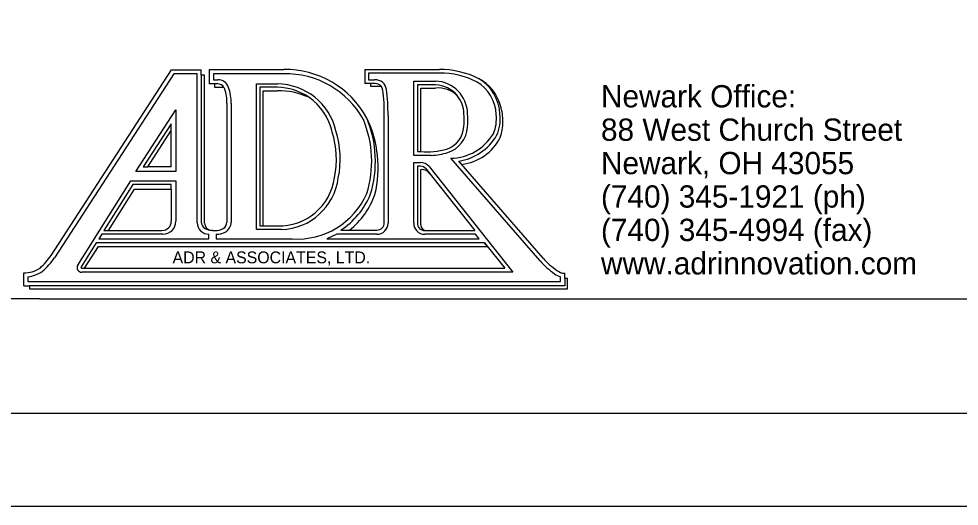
# Model space of a CAD drawing. Extents: x 0 to 2329303, y 0 to 694397.
# Drawn here: x 2.57 to 7.64, y 0 to 2.63 of the extents above; entities that cross this region are included whole.
import ezdxf

# ---------------------------------------------------------------- set-up
doc = ezdxf.new("R2010")
doc.units = 0
for name, color, linetype in [('SH_Border', 7, 'Continuous'), ('SH_Cut_Line', 7, 'Continuous'), ('SH_Data', 7, 'Continuous')]:
    doc.layers.add(name, color=color, linetype=linetype)

msp = doc.modelspace()

# ---------------------------------------------------------------- linework, layer by layer
at = {"layer": 'SH_Border'}
msp.add_lwpolyline([(1.5, 21.5), (33.5, 21.5), (33.5, 0.5), (1.5, 0.5)], close=True, dxfattribs=at)
at = {"layer": 'SH_Cut_Line'}
msp.add_lwpolyline([(0, 0), (34, 0), (34, 22), (0, 22)], close=True, dxfattribs=at)
at = {"layer": 'SH_Data'}
for p, q in [((2.7482, 1.3509), (3.3982, 2.3517)), ((3.3982, 2.3517), (3.5581, 2.3517)), ((3.5581, 2.3218), (3.5581, 2.3517)), ((3.6, 2.3529), (3.6, 2.2749)), ((3.6, 2.3529), (4.0021, 2.3529)), ((4.44, 2.3529), (4.44, 2.2778)), ((4.44, 2.3529), (4.8421, 2.3529)), ((3.63, 2.2749), (3.6, 2.2749)), ((4.47, 2.2778), (4.44, 2.2778)), ((3.6962, 2.1694), (3.6962, 1.5311)), ((4.5443, 1.5273), (4.5443, 2.1043)), ((3.3962, 1.828), (3.3962, 2.0237)), ((3.3962, 1.828), (3.2691, 1.828)), ((5.3998, 1.336), (4.9458, 1.8587)), ((4.7723, 1.814), (5.0329, 1.4852)), ((3.3962, 1.708), (3.3962, 1.5353)), ((3.0573, 1.4853), (3.3462, 1.4853)), ((3.6177, 1.4852), (3.6118, 1.4857)), ((3.6177, 1.4852), (3.6324, 1.4852)), ((3.8913, 1.5107), (3.9682, 1.5107)), ((4.3102, 1.4873), (4.5043, 1.4873)), ((4.7627, 1.4852), (5.0329, 1.4852)), ((5.0844, 1.4193), (5.1932, 1.2816)), ((2.9289, 1.2816), (5.1932, 1.2816)), ((2.6013, 1.1881), (2.6013, 1.2567)), ((5.5167, 1.2268), (5.5167, 1.2553)), ((2.6013, 1.1881), (2.6318, 1.1881)), ((2.6879, 1.1163), (2.2843, 1.1163)), ((2.6879, 1.1163), (7.8956, 1.1163))]:
    msp.add_line(p, q, dxfattribs=at)
for points in [[(4.8421, 2.3329), (4.46, 2.3329), (4.46, 2.2978), (4.4918, 2.2978)], [(3.5361, 1.5275), (3.5361, 2.3297), (3.4101, 2.3297), (2.7667, 1.3389)], [(3.5761, 1.5255), (3.5761, 2.3218), (3.5581, 2.3218), (3.5581, 1.5311)], [(4.0021, 2.3297), (3.6232, 2.3297), (3.6232, 2.2975), (3.6464, 2.2975)], [(4.7027, 2.2904), (4.8216, 2.2904)], [(4.7974, 1.8901), (4.7027, 1.8901), (4.7027, 2.2904)], [(3.6464, 2.2749), (3.63, 2.2749), (3.63, 2.2569), (3.6798, 2.2569)], [(3.8556, 1.49), (3.8556, 2.2749), (3.9682, 2.2749)], [(3.9682, 2.2569), (3.8733, 2.2569), (3.8733, 1.5107), (3.8913, 1.5107), (3.8913, 2.2386), (3.9682, 2.2386)], [(4.4864, 2.2778), (4.47, 2.2778), (4.47, 2.2623), (4.5279, 2.2623)], [(4.8212, 2.2704), (4.7227, 2.2704), (4.7227, 1.9117)], [(4.7407, 1.9101), (4.7407, 2.2524), (4.8212, 2.2524)], [(3.4212, 1.803), (3.2052, 1.803), (3.4212, 2.1356), (3.4212, 1.803)], [(3.7188, 2.1694), (3.7188, 2.1685), (3.7188, 1.5311)], [(4.5643, 2.1041), (4.5643, 1.5252)], [(3.3962, 2.0237), (3.3962, 2.0604), (3.2453, 1.828), (3.2691, 1.828), (3.3962, 2.0237)], [(4.7857, 1.8293), (5.2369, 1.2601), (2.9134, 1.2601)], [(4.7027, 1.5252), (4.7027, 1.852), (4.7387, 1.852)], [(4.7387, 1.832), (4.7227, 1.832), (4.7227, 1.5252)], [(5.3836, 1.3211), (4.9027, 1.8749)], [(4.9458, 1.8587), (4.9608, 1.8414)], [(4.7407, 1.5152), (4.7407, 1.814), (4.7433, 1.814)], [(4.7903, 1.7913), (4.7701, 1.8168)], [(2.8922, 1.2985), (3.1787, 1.753), (3.4212, 1.753), (3.4212, 1.5353)], [(3.3962, 1.708), (3.3962, 1.733), (3.1897, 1.733), (3.0336, 1.4853), (3.0573, 1.4853), (3.1976, 1.708), (3.3962, 1.708)], [(3.9896, 1.49), (3.8556, 1.49)], [(4.3102, 1.4873), (4.3567, 1.4873)], [(4.7627, 1.4852), (4.7707, 1.4852)], [(5.1002, 1.3993), (5.0844, 1.4193), (2.992, 1.4193), (2.9101, 1.2892)], [(3.3512, 1.4653), (3.0213, 1.4653), (3.0056, 1.4403), (3.5984, 1.4403), (3.5984, 1.4653)], [(3.6387, 1.4653), (3.6387, 1.4403), (4.0488, 1.4403)], [(4.5043, 1.4652), (4.2885, 1.4652), (4.2339, 1.4403), (5.0563, 1.4403), (5.0366, 1.4652), (4.7627, 1.4652)], [(2.9143, 1.2816), (2.9289, 1.2816), (3.0031, 1.3993), (5.1002, 1.3993)], [(2.6233, 1.236), (2.6233, 1.2101), (5.4947, 1.2101), (5.4947, 1.2361)], [(5.5167, 1.2268), (5.5167, 1.1881), (2.6318, 1.1881), (2.6318, 1.1717), (5.5315, 1.1717), (5.5315, 1.2268), (5.5167, 1.2268)]]:
    msp.add_lwpolyline(points, dxfattribs=at)
for centre, radius, start, end in [((4.0092, 1.8512), 0.5017, 28.5037, 90.8094), ((4.847, 1.9007), 0.4522, 62.8944, 90.6455), ((4.8473, 1.9019), 0.431, 63.1652, 90.6924), ((3.6464, 2.2349), 0.0626, 19.9599, 90), ((4.0128, 1.8511), 0.4787, 28.9697, 91.2754), ((4.4889, 2.2142), 0.0836, 56.3608, 88.0126), ((4.495, 2.2381), 0.0608, 6.9031, 48.6696), ((4.8134, 2.1105), 0.1801, 1.5931, 87.3658), ((4.9344, 2.1021), 0.2134, 2.1717, 59.7559), ((4.946, 2.0969), 0.2324, 14.8093, 62.8819), ((4.9344, 2.1021), 0.2334, 2.3391, 59.7559), ((4.946, 2.0969), 0.2324, 14.8093, 62.8819), ((4.9344, 2.1021), 0.2334, 2.3391, 59.7559), ((3.6464, 2.2349), 0.04, 33.367, 90), ((3.6464, 2.2349), 0.04, 19.9599, 33.367), ((3.4897, 2.178), 0.2067, 357.6357, 19.9599), ((3.4897, 2.178), 0.2293, 357.8689, 19.9599), ((3.9661, 1.9493), 0.3256, 12.9457, 89.6392), ((3.9638, 1.9496), 0.3073, 55.708, 89.1774), ((3.9693, 1.8209), 0.4177, 66.3384, 90.1529), ((4.4889, 2.2142), 0.0636, 57.6105, 92.2784), ((4.495, 2.2381), 0.0408, 36.3055, 46.8401), ((4.495, 2.2381), 0.0408, 6.5993, 36.3055), ((3.6945, 2.1203), 0.85, 358.9246, 8.2892), ((3.6945, 2.1203), 0.87, 358.937, 8.2716), ((4.8134, 2.1105), 0.1601, 39.5541, 87.2061), ((4.8356, 2.1069), 0.1462, 46.2019, 95.6746), ((3.9638, 1.9496), 0.3073, 12.4839, 55.708), ((4.8134, 2.1105), 0.1601, 1.5931, 39.5541), ((4.9219, 2.0761), 0.2614, 358.8465, 17.8591), ((3.8896, 1.8582), 0.5868, 342.7269, 22.5268), ((3.9047, 1.8246), 0.6068, 346.2054, 26.0053), ((3.8896, 1.8582), 0.6068, 342.7269, 22.5268), ((3.8896, 1.8582), 0.6068, 342.7269, 22.5268), ((3.9047, 1.8246), 0.6068, 346.2054, 26.0053), ((4.5969, 2.0827), 0.3779, 354.0254, 4.8885), ((4.6077, 2.0826), 0.3871, 354.0167, 4.8798), ((4.9391, 2.088), 0.2098, 336.9308, 6.0804), ((4.9391, 2.088), 0.2298, 336.5619, 5.9102), ((4.9391, 2.088), 0.2298, 336.5619, 5.9102), ((4.8385, 2.0514), 0.1345, 288.9475, 356.593), ((4.8375, 2.0522), 0.1555, 288.6824, 356.328), ((4.9411, 2.0671), 0.2422, 340.715, 0.8874), ((4.9411, 2.0671), 0.2422, 340.715, 0.8874), ((3.7992, 1.8701), 0.487, 348.269, 17.4361), ((3.8022, 1.8702), 0.5047, 348.3549, 17.522), ((4.8983, 2.1489), 0.2741, 270.9085, 328.5097), ((4.8983, 2.1489), 0.2941, 279.2997, 328.7949), ((4.8983, 2.1489), 0.2941, 279.2997, 328.7949), ((4.9306, 2.1074), 0.2677, 276.4841, 333.2931), ((4.9306, 2.1074), 0.2677, 276.4841, 333.2931), ((4.7687, 2.3469), 0.4377, 263.9631, 266.3281), ((4.7687, 2.3469), 0.4377, 266.3281, 285.024), ((4.7687, 2.3469), 0.4577, 273.5907, 285.024), ((4.7387, 1.792), 0.06, 38.4038, 90), ((4.7387, 1.792), 0.04, 38.4038, 90), ((4.7433, 1.754), 0.06, 38.4038, 90), ((3.9789, 1.8102), 0.2997, 267.9548, 352.4953), ((3.9789, 1.8102), 0.3204, 271.9132, 352.4953), ((4.0753, 1.8488), 0.4093, 266.2973, 336.2434), ((4.075, 1.8445), 0.4277, 303.356, 337.0819), ((4.0907, 1.8222), 0.4277, 308.4519, 340.5604), ((3.3462, 1.5353), 0.05, 270, 0), ((3.3512, 1.5353), 0.07, 270, 0), ((3.5983, 1.5275), 0.0622, 180, 270.0369), ((3.5981, 1.5311), 0.04, 180, 241.4738), ((3.6161, 1.5255), 0.04, 180, 263.7978), ((3.6562, 1.5311), 0.04, 298.5263, 0), ((3.6562, 1.5311), 0.0626, 298.5263, 0), ((4.5043, 1.5273), 0.04, 270, 0), ((4.5043, 1.5252), 0.06, 270, 0), ((4.7627, 1.5252), 0.06, 180, 270), ((4.7627, 1.5252), 0.04, 180, 270), ((3.6214, 1.5739), 0.0887, 241.4738, 263.7978), ((3.6329, 1.5739), 0.0887, 269.6371, 298.5263), ((3.6435, 1.5546), 0.0893, 266.9745, 298.5204), ((4.7707, 1.5152), 0.03, 180, 270), ((2.4817, 1.5251), 0.3184, 310.5502, 326.8355), ((2.4817, 1.5251), 0.3404, 310.339, 326.8355), ((5.7425, 1.6505), 0.4871, 222.5427, 234.756), ((5.7425, 1.6505), 0.4651, 222.5427, 234.839), ((2.602, 1.4122), 0.1555, 269.7467, 303.9115), ((2.9134, 1.2851), 0.025, 147.7842, 270), ((2.9143, 1.2866), 0.005, 147.7838, 270), ((5.5169, 1.3222), 0.0669, 230.9326, 269.855), ((2.602, 1.4122), 0.1775, 276.8971, 304.3301), ((5.5169, 1.3222), 0.0889, 231.4448, 255.561)]:
    msp.add_arc(centre, radius, start, end, dxfattribs=at)

# ---------------------------------------------------------------- texts
for s, height, p in [('Newark Office:', 0.12, (5.7122, 2.1486)), ('88 West Church Street', 0.12, (5.7122, 1.9686)), ('Newark, OH 43055', 0.12, (5.7122, 1.7886)), ('(740) 345-1921 (ph)', 0.12, (5.7122, 1.6086)), ('(740) 345-4994 (fax)', 0.12, (5.7122, 1.4286)), ('ADR & ASSOCIATES, LTD.', 0.064, (3.4031, 1.3085)), ('www.adrinnovation.com', 0.12, (5.7122, 1.2486))]:
    msp.add_text(s, height=height, dxfattribs=at).set_placement(p)

doc.saveas('drawing.dxf')
